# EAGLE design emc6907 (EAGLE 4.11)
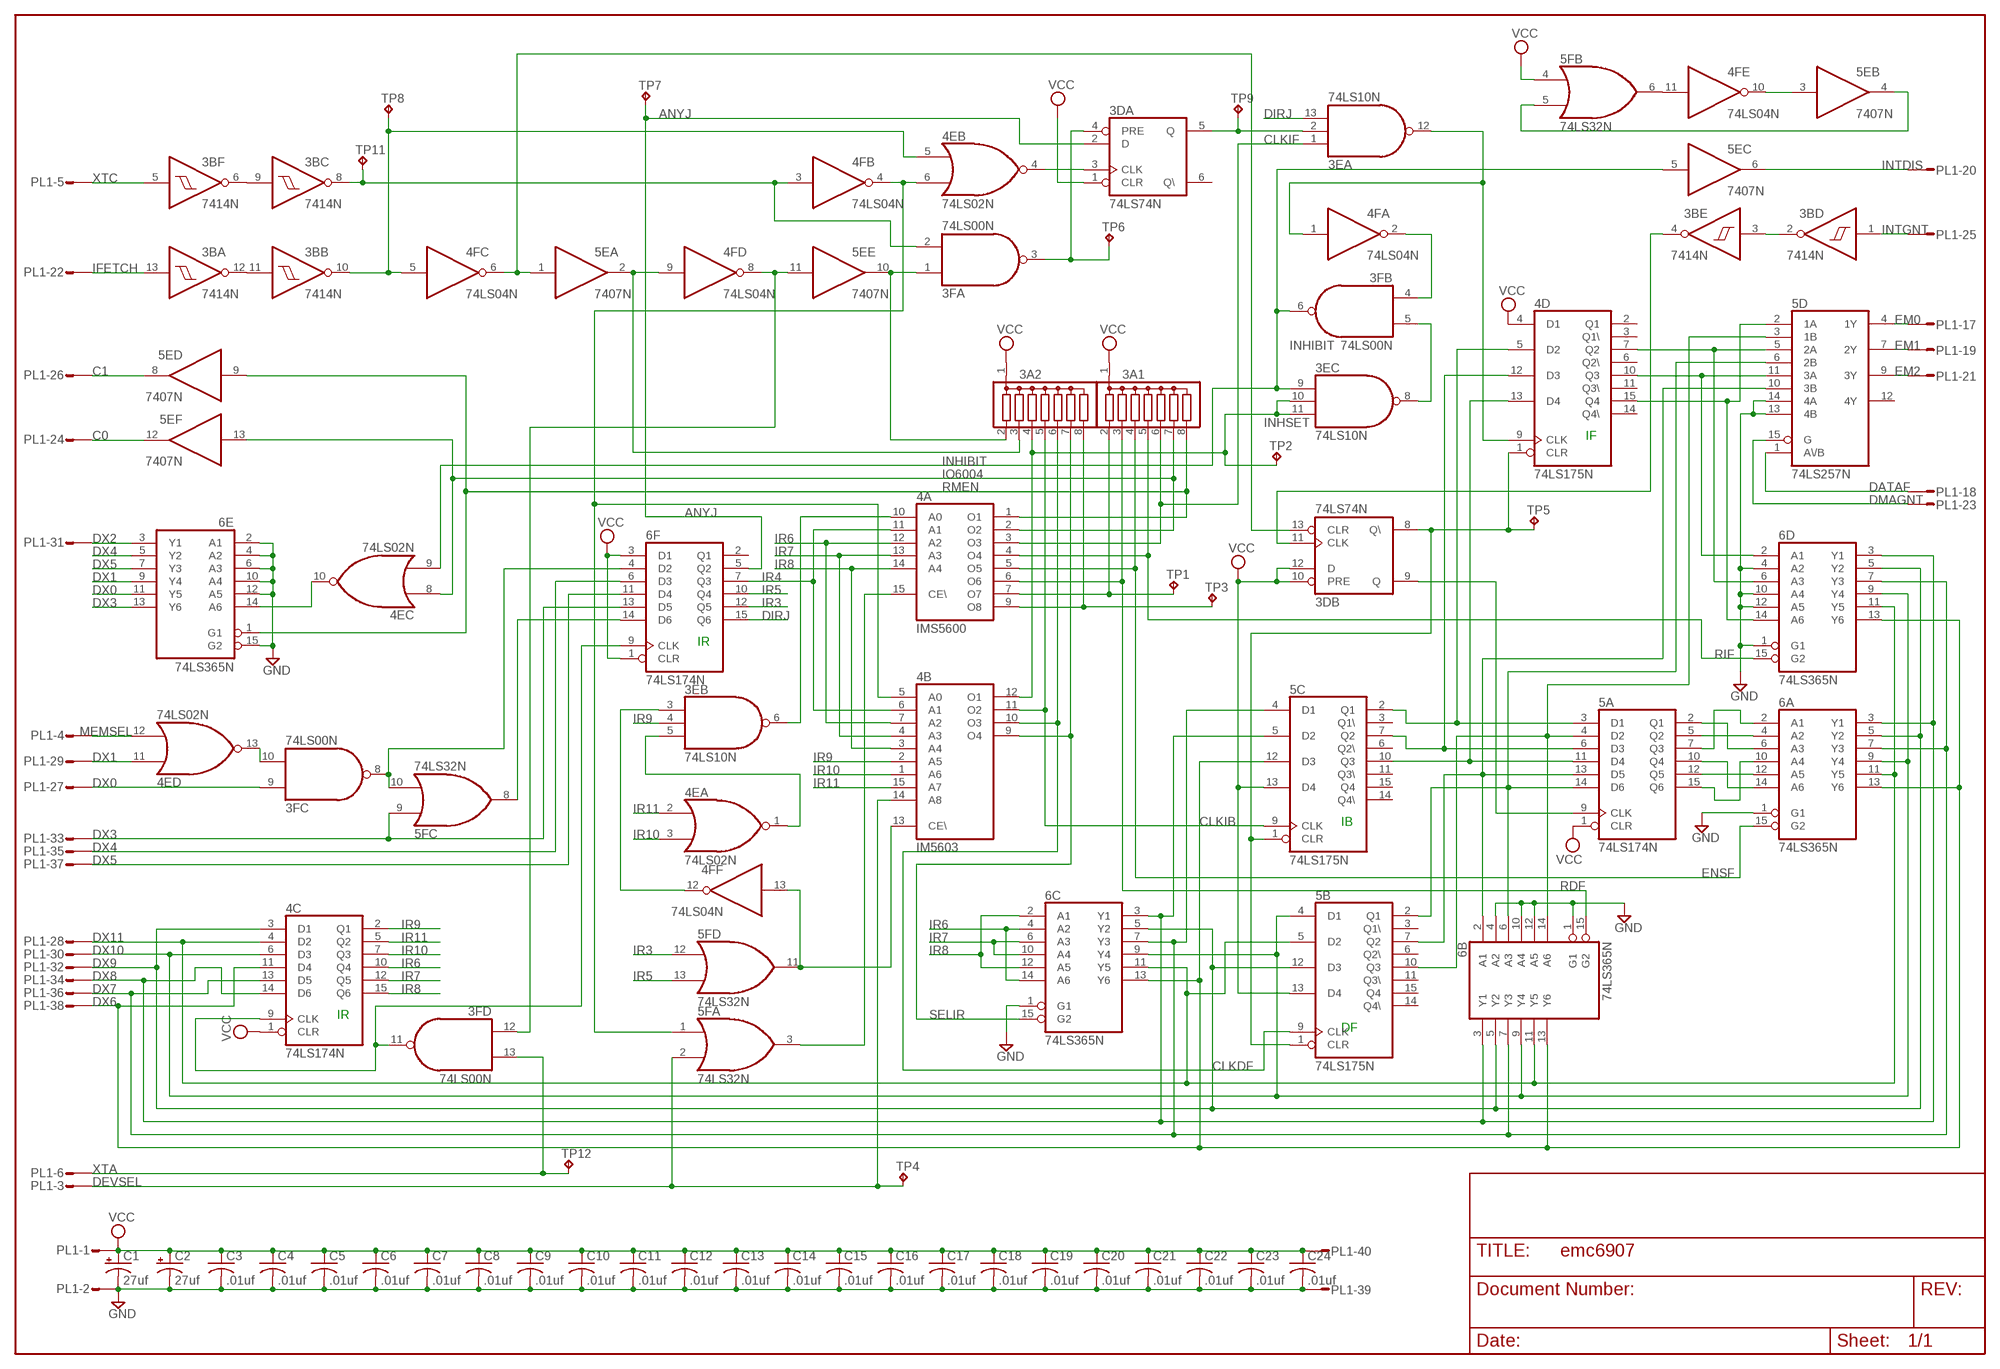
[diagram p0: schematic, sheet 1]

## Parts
3A1  G07R  [SIL8]
3A2  G07R  [SIL8]
3B  7414N  [DIL14]
3D  74LS74N  [DIL14]
3E  74LS10N  [DIL14]
3F  74LS00N  [DIL14]
4A  IMS5600  5600  [DIL16]
4B  IM5603  5306  [DIL16]
4C  74LS174N  [DIL16]
4D  74LS175N  [DIL16]
4E  74LS02N  [DIL14]
4F  74LS04N  [DIL14]
5A  74LS174N  [DIL16]
5B  74LS175N  [DIL16]
5C  74LS175N  [DIL16]
5D  74LS257N  [DIL16]
5E  7407N  [DIL14]
5F  74LS32N  [DIL14]
6A  74LS365N  [DIL16]
6B  74LS365N  [DIL16]
6C  74LS365N  [DIL16]
6D  74LS365N  [DIL16]
6E  74LS365N  [DIL16]
6F  74LS174N  [DIL16]
C1  27uf  CPOL-USE22-6AXIAL  [E22-6]
C2  27uf  CPOL-USE22-6AXIAL  [E22-6]
C3  .01uf  C-US050-025X075  [C050-025X075]
C4  .01uf  C-US050-025X075  [C050-025X075]
C5  .01uf  C-US050-025X075  [C050-025X075]
C6  .01uf  C-US050-025X075  [C050-025X075]
C7  .01uf  C-US050-025X075  [C050-025X075]
C8  .01uf  C-US050-025X075  [C050-025X075]
C9  .01uf  C-US050-025X075  [C050-025X075]
C10  .01uf  C-US050-025X075  [C050-025X075]
C11  .01uf  C-US050-025X075  [C050-025X075]
C12  .01uf  C-US050-025X075  [C050-025X075]
C13  .01uf  C-US050-025X075  [C050-025X075]
C14  .01uf  C-US050-025X075  [C050-025X075]
C15  .01uf  C-US050-025X075  [C050-025X075]
C16  .01uf  C-US050-025X075  [C050-025X075]
C17  .01uf  C-US050-025X075  [C050-025X075]
C18  .01uf  C-US050-025X075  [C050-025X075]
C19  .01uf  C-US050-025X075  [C050-025X075]
C20  .01uf  C-US050-025X075  [C050-025X075]
C21  .01uf  C-US050-025X075  [C050-025X075]
C22  .01uf  C-US050-025X075  [C050-025X075]
C23  .01uf  C-US050-025X075  [C050-025X075]
C24  .01uf  C-US050-025X075  [C050-025X075]
PL1  40VS  [40V]
TP1  TPPAD1-13  [P1-13]
TP2  TPPAD1-13  [P1-13]
TP3  TPPAD1-13  [P1-13]
TP4  TPPAD1-13  [P1-13]
TP5  TPPAD1-13  [P1-13]
TP6  TPPAD1-13  [P1-13]
TP7  TPPAD1-13  [P1-13]
TP8  TPPAD1-13  [P1-13]
TP9  TPPAD1-13  [P1-13]
TP11  TPPAD1-13  [P1-13]
TP12  TPPAD1-13  [P1-13]

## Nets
ANYJ: 3D.2(A:D) 6F.5(Q2) TP7.1(TP)
C0: 5E.12(F:O) PL1.24
C1: 5E.8(D:O) PL1.26
CLKDF: 3A2.6 4B.10(O3) 5B.9(CLK)
CLKIB: 3A2.5 4B.11(O2) 5C.9(CLK)
CLKIF: 3A1.6 3E.1(A:I0) 4A.3(O3)
DATAF: 5D.1(A\/B) PL1.18
DEVSEL: 4B.14(A8) 5F.2(A:I1) PL1.3 TP4.1(TP)
DIRJ: 3E.13(A:I2) 6F.15(Q6)
DMAGNT: 5D.15(G) PL1.23
DX0: 3F.9(C:I0) 6E.11(Y5) PL1.27
DX1: 4E.11(D:I0) 6E.9(Y4) PL1.29
DX2: 6E.3(Y1) PL1.31
DX3: 5F.9(C:I0) 6E.13(Y6) 6F.13(D5) PL1.33
DX4: 6E.5(Y2) 6F.6(D3) PL1.35
DX5: 6E.7(Y3) 6F.11(D4) PL1.37
DX6: 4C.11(D4) 5C.12(D3) 6A.13(Y6) 6B.13(Y6) 6C.13(Y6) 6D.13(Y6) PL1.38
DX7: 4C.13(D5) 5C.4(D1) 6A.7(Y3) 6B.7(Y3) 6C.7(Y3) 6D.7(Y3) PL1.36
DX8: 4C.14(D6) 5C.5(D2) 6A.3(Y1) 6B.3(Y1) 6C.3(Y1) 6D.3(Y1) PL1.34
DX9: 4C.3(D1) 5B.12(D3) 6A.5(Y2) 6B.5(Y2) 6C.5(Y2) 6D.5(Y2) PL1.32
DX10: 4C.6(D3) 5B.4(D1) 6A.9(Y4) 6B.9(Y4) 6C.9(Y4) 6D.9(Y4) PL1.30
DX11: 4C.4(D2) 5B.5(D2) 6A.11(Y5) 6B.11(Y5) 6C.11(Y5) 6D.11(Y5) PL1.28
EM0: 5D.4(1Y) PL1.17
EM1: 5D.7(2Y) PL1.19
EM2: 5D.9(3Y) PL1.21
ENSF: 3A1.4 4A.5(O5) 6A.15(G2)
GND: 5D.13(4B) 5D.14(4A) 6A.1(G1) 6B.1(G1) 6B.4(A2) 6B.10(A4) 6B.12(A5) 6C.1(G1) 6D.1(G1) 6D.4(A2) 6D.10(A4) 6D.12(A5) 6E.2(A1) 6E.4(A2) 6E.6(A3) 6E.10(A4) 6E.12(A5) 6E.15(G2) C1.- C2.- C3.2 C4.2 C5.2 C6.2 C7.2 C8.2 C9.2 C10.2 C11.2 C12.2 C13.2 C14.2 C15.2 C16.2 C17.2 C18.2 C19.2 C20.2 C21.2 C22.2 C23.2 C24.2 PL1.2 PL1.39
IFETCH: 3B.13(A:I) PL1.22
INHIBIT: 3E.9(C:I0) 3F.6(B:O) 4E.9(C:I1) 5E.5(C:I)
INHSET: 3A2.4 3E.10(C:I1) 3E.11(C:I2) 4B.12(O1) TP2.1(TP)
INTDIS: 5E.6(C:O) PL1.20
INTGNT: 3B.1(D:I) PL1.25
IO6004: 3A1.7 4A.2(O2) 4E.8(C:I0) 5E.13(F:I)
IR3: 5F.12(D:I0) 6F.12(Q5)
IR4: 4A.11(A1) 4B.6(A1) 6F.7(Q3)
IR5: 5F.13(D:I1) 6F.10(Q4)
IR6: 4A.12(A2) 4B.7(A2) 4C.10(Q4) 6C.4(A2) 6C.14(A6)
IR7: 4A.13(A3) 4B.4(A3) 4C.12(Q5) 6C.6(A3) 6C.10(A4)
IR8: 4A.14(A4) 4B.3(A4) 4C.15(Q6) 6C.2(A1) 6C.12(A5)
IR9: 3E.4(B:I1) 4B.2(A5) 4C.2(Q1)
IR10: 4B.1(A6) 4C.7(Q3) 4E.3(A:I1)
IR11: 4B.15(A7) 4C.5(Q2) 4E.2(A:I0)
LOADIR: 3F.11(D:O) 4C.9(CLK) 6F.9(CLK)
MEMSEL: 4E.12(D:I1) PL1.4
N$1: 3B.11(B:I) 3B.12(A:O)
N$2: 3B.6(F:O) 3B.9(C:I)
N$3: 3B.8(C:O) 3F.2(A:I1) 4F.3(B:I) TP11.1(TP)
N$4: 3B.10(B:O) 4E.5(B:I0) 4F.5(C:I) TP8.1(TP)
N$5: 3D.13(B:CLR) 4F.6(C:O) 5E.1(A:I)
N$6: 3D.5(A:Q) 3E.2(A:I1) TP9.1(TP)
N$7: 3A2.2 3F.1(A:I0) 5E.10(E:O)
N$8: 3F.12(D:I0) 4F.8(D:O) 5E.11(E:I)
N$9: 3A2.3 4F.9(D:I) 5E.2(A:O)
N$10: 4B.5(A0) 4E.6(B:I1) 4F.4(B:O) 5F.1(A:I0)
N$11: 3D.3(A:CLK) 4E.4(B:O)
N$12: 3D.4(A:PRE) 3F.3(A:O) TP6.1(TP)
N$13: 4F.11(E:I) 5F.6(B:O)
N$14: 3F.10(C:I1) 4E.13(D:O)
N$15: 4E.10(C:O) 6E.14(A6)
N$16: 5E.4(B:O) 5F.5(B:I1)
N$17: 4F.10(E:O) 5E.3(B:I)
N$18: 3F.8(C:O) 5F.10(C:I1) 6F.4(D2)
N$19: 5F.8(C:O) 6F.14(D6)
N$20: 4B.13(CE\) 4F.13(F:I) 5F.11(D:O)
N$28: 3A1.2 4A.7(O7) TP1.1(TP)
N$29: 3A2.8 4A.9(O8) TP3.1(TP)
N$35: 3E.3(B:I0) 4F.12(F:O)
N$36: 3E.6(B:O) 4A.10(A0)
N$37: 4A.15(CE\) 5F.3(A:O)
N$38: 5A.2(Q1) 6A.6(A3)
N$39: 3E.5(B:I2) 4E.1(A:O)
N$40: 5A.10(Q4) 6A.14(A6)
N$41: 5A.7(Q3) 6A.2(A1)
N$42: 5A.5(Q2) 6A.4(A2)
N$43: 5A.15(Q6) 6A.10(A4)
N$44: 5A.12(Q5) 6A.12(A5)
N$45: 4D.15(Q4) 5D.2(1A) 6D.14(A6)
N$46: 4D.10(Q3) 5D.11(3A) 6D.2(A1)
N$47: 4D.7(Q2) 5D.5(2A) 6D.6(A3)
N$48: 3D.8(B:Q\) 4D.1(CLR) 5B.1(CLR) 5C.1(CLR) TP5.1(TP)
N$50: 4D.13(D4) 5A.11(D4) 5C.10(Q3)
N$51: 4D.5(D2) 5A.3(D1) 5C.2(Q1)
N$52: 4D.12(D3) 5A.6(D3) 5C.7(Q2)
N$53: 5A.4(D2) 5B.10(Q3) 5D.3(1B) 6B.14(A6)
N$54: 5A.14(D6) 5B.2(Q1) 5D.6(2B) 6B.6(A3)
N$55: 5A.13(D5) 5B.7(Q2) 5D.10(3B) 6B.2(A1)
N$59: 3D.9(B:Q) 5A.9(CLK)
N$61: 3E.12(A:O) 4D.9(CLK) 4F.1(A:I)
N$70: 3E.8(C:O) 3F.5(B:I1)
N$71: 3F.4(B:I0) 4F.2(A:O)
N$72: 3B.2(D:O) 3B.3(E:I)
N$74: 3B.4(E:O) 3D.11(B:CLK)
RDF: 3A1.3 4A.6(O6) 6B.15(G2)
RIF: 3A1.5 4A.4(O4) 6D.15(G2)
RMEN: 3A1.8 4A.1(O1) 5E.9(D:I) 6E.1(G1)
SELIR: 3A2.7 4B.9(O4) 6C.15(G2)
VCC: 3A1.1 3A2.1 3D.1(A:CLR) 3D.10(B:PRE) 3D.12(B:D) 4C.1(CLR) 4D.4(D1) 5A.1(CLR) 5B.13(D4) 5C.13(D4) 5F.4(B:I0) 6F.1(CLR) 6F.3(D1) C1.+ C2.+ C3.1 C4.1 C5.1 C6.1 C7.1 C8.1 C9.1 C10.1 C11.1 C12.1 C13.1 C14.1 C15.1 C16.1 C17.1 C18.1 C19.1 C20.1 C21.1 C22.1 C23.1 C24.1 PL1.1 PL1.40
XTA: 3F.13(D:I1) PL1.6 TP12.1(TP)
XTC: 3B.5(F:I) PL1.5
Unconnected: 3D.6(A:Q\) 4D.2(Q1) 4D.3(Q1\) 4D.6(Q2\) 4D.11(Q3\) 4D.14(Q4\) 5B.3(Q1\) 5B.6(Q2\) 5B.11(Q3\) 5B.14(Q4\) 5B.15(Q4) 5C.3(Q1\) 5C.6(Q2\) 5C.11(Q3\) 5C.14(Q4\) 5C.15(Q4) 5D.12(4Y) 6F.2(Q1) PL1.7 PL1.8 PL1.9 PL1.10 PL1.11 PL1.12 PL1.13 PL1.14 PL1.15 PL1.16

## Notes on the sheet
- IF
- IR
- IB
- IR
- DF

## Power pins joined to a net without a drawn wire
GND: 3B.7(P:GND) 3D.7(P:GND) 3E.7(P:GND) 3F.7(P:GND) 4A.8(GND) 4B.8(GND) 4C.8(GND) 4D.8(GND) 4E.7(P:GND) 4F.7(P:GND) 5A.8(GND) 5B.8(GND) 5C.8(GND) 5D.8(GND) 5E.7(P:GND) 5F.7(P:GND) 6A.8(GND) 6B.8(GND) 6C.8(GND) 6D.8(GND) 6E.8(GND) 6F.8(GND)
VCC: 3B.14(P:VCC) 3D.14(P:VCC) 3E.14(P:VCC) 3F.14(P:VCC) 4A.16(VCC) 4B.16(VCC) 4C.16(VCC) 4D.16(VCC) 4E.14(P:VCC) 4F.14(P:VCC) 5A.16(VCC) 5B.16(VCC) 5C.16(VCC) 5D.16(VCC) 5E.14(P:VCC) 5F.14(P:VCC) 6A.16(VCC) 6B.16(VCC) 6C.16(VCC) 6D.16(VCC) 6E.16(VCC) 6F.16(VCC)

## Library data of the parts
3A1 3A2 = resistor-sil:G07R: SIL RESISTOR
3B = 74xx-jameco:74*14: Hex schmitt trigger INVERTER
3D = 74xx-jameco:74*74: Dual D type positive edge triggered FLIP FLOP, preset and clear
3E = 74xx-jameco:74*10: Triple 3-input NAND gate
3F = 74xx-jameco:74*00: Quad 2-input NAND gate
4A = memory:5600: MEMORY
4B = memory:5306: MEMORY
4C 5A 6F = 74xx-jameco:74*174: Hex D type FLIP FLOP, clear
4D 5B 5C = 74xx-jameco:74*175: Qadruple D type FLIP FLOP, clear
4E = 74xx-jameco:74*02: Quad 2-input NOR gate
4F = 74xx-jameco:74*04: Hex INVERTER
5D = 74xx-jameco:74*257: Quadruple 2-to 1 line data SELECTOR/MULTIPLEXER
5E = 74xx-jameco:74*07: Hex BUFFER, open collector high-voltage output
5F = 74xx-jameco:74*32: Quad 2-input OR gate
6A 6B 6C 6D 6E = 74xx-jameco:74*365: Hex BUS DRIVER, 3-state
C1 C2 = rcl:CPOL-US: POLARIZED CAPACITOR, American symbol
C3-C24 = rcl:C-US: CAPACITOR, American symbol
PL1 = con-harting-v:40VS: CONNECTOR
TP1-TP9 TP11 TP12 = testpad:TP

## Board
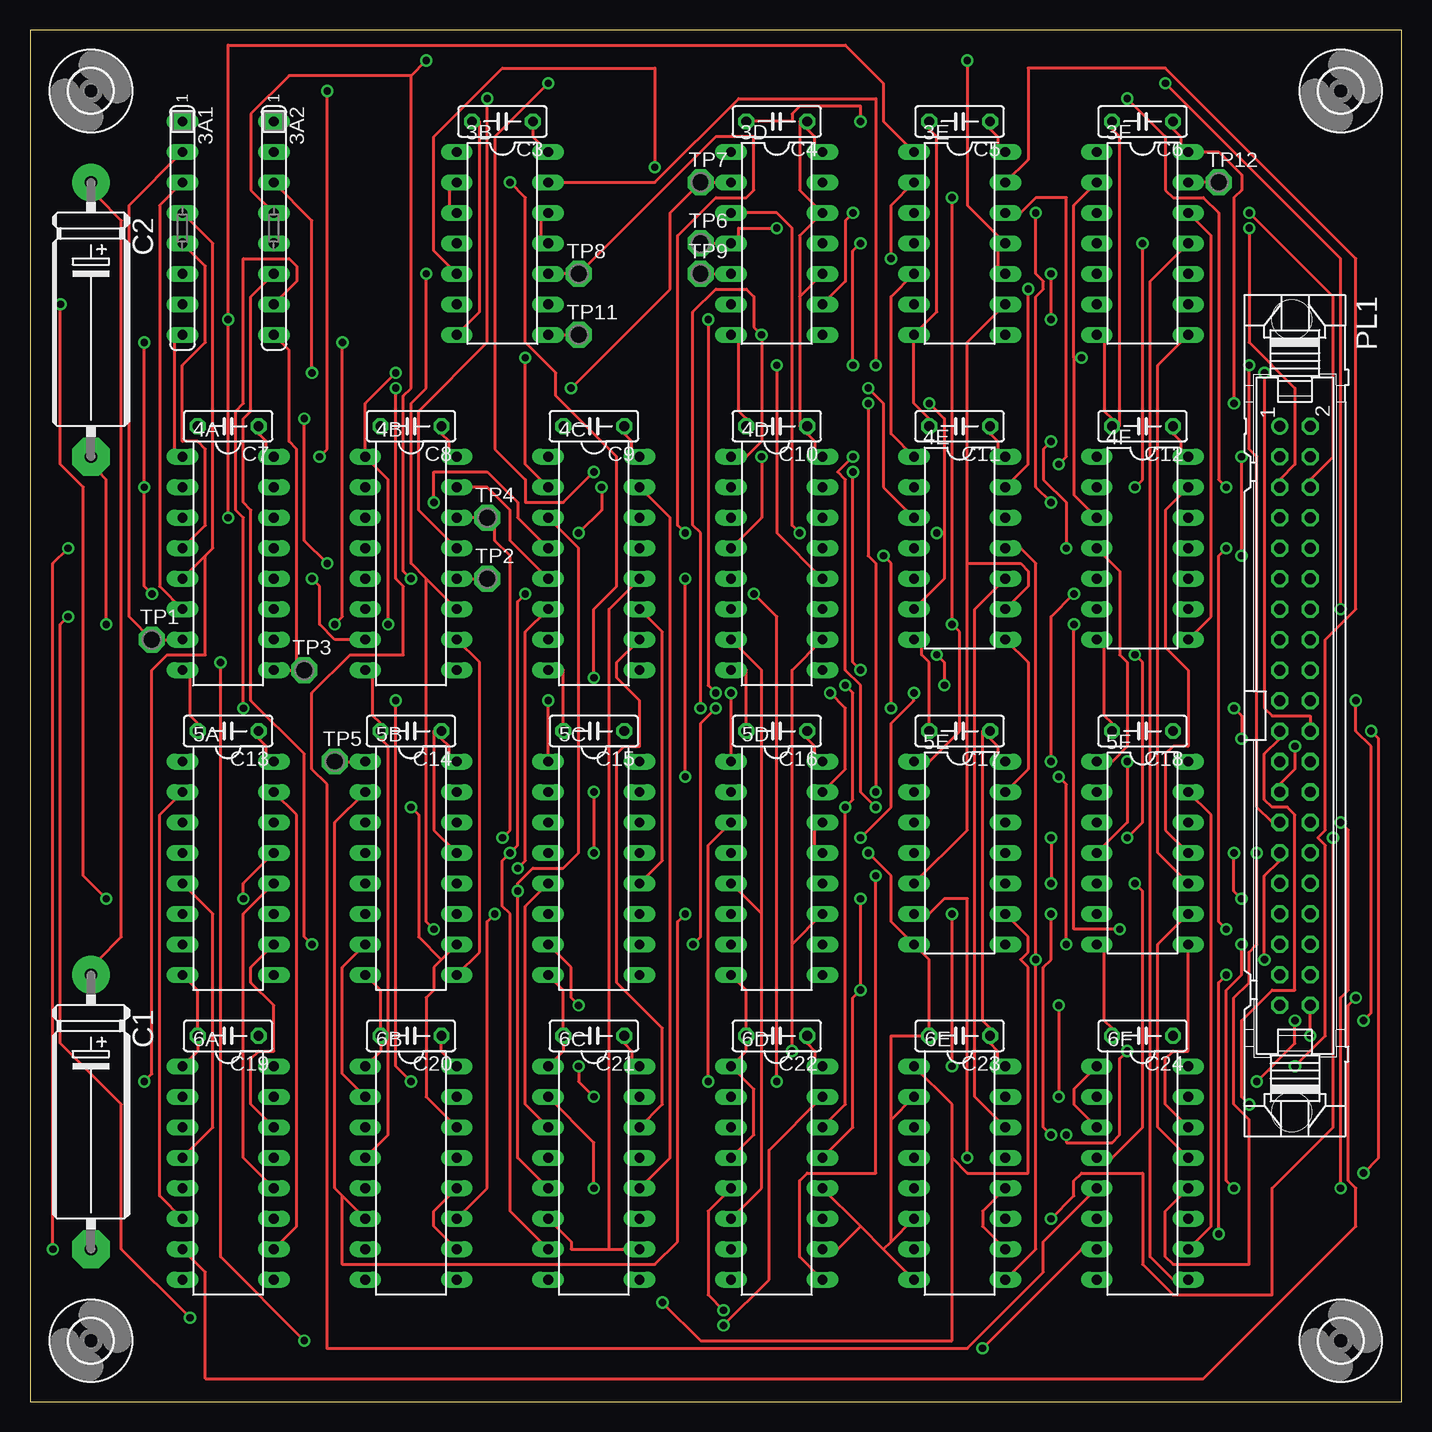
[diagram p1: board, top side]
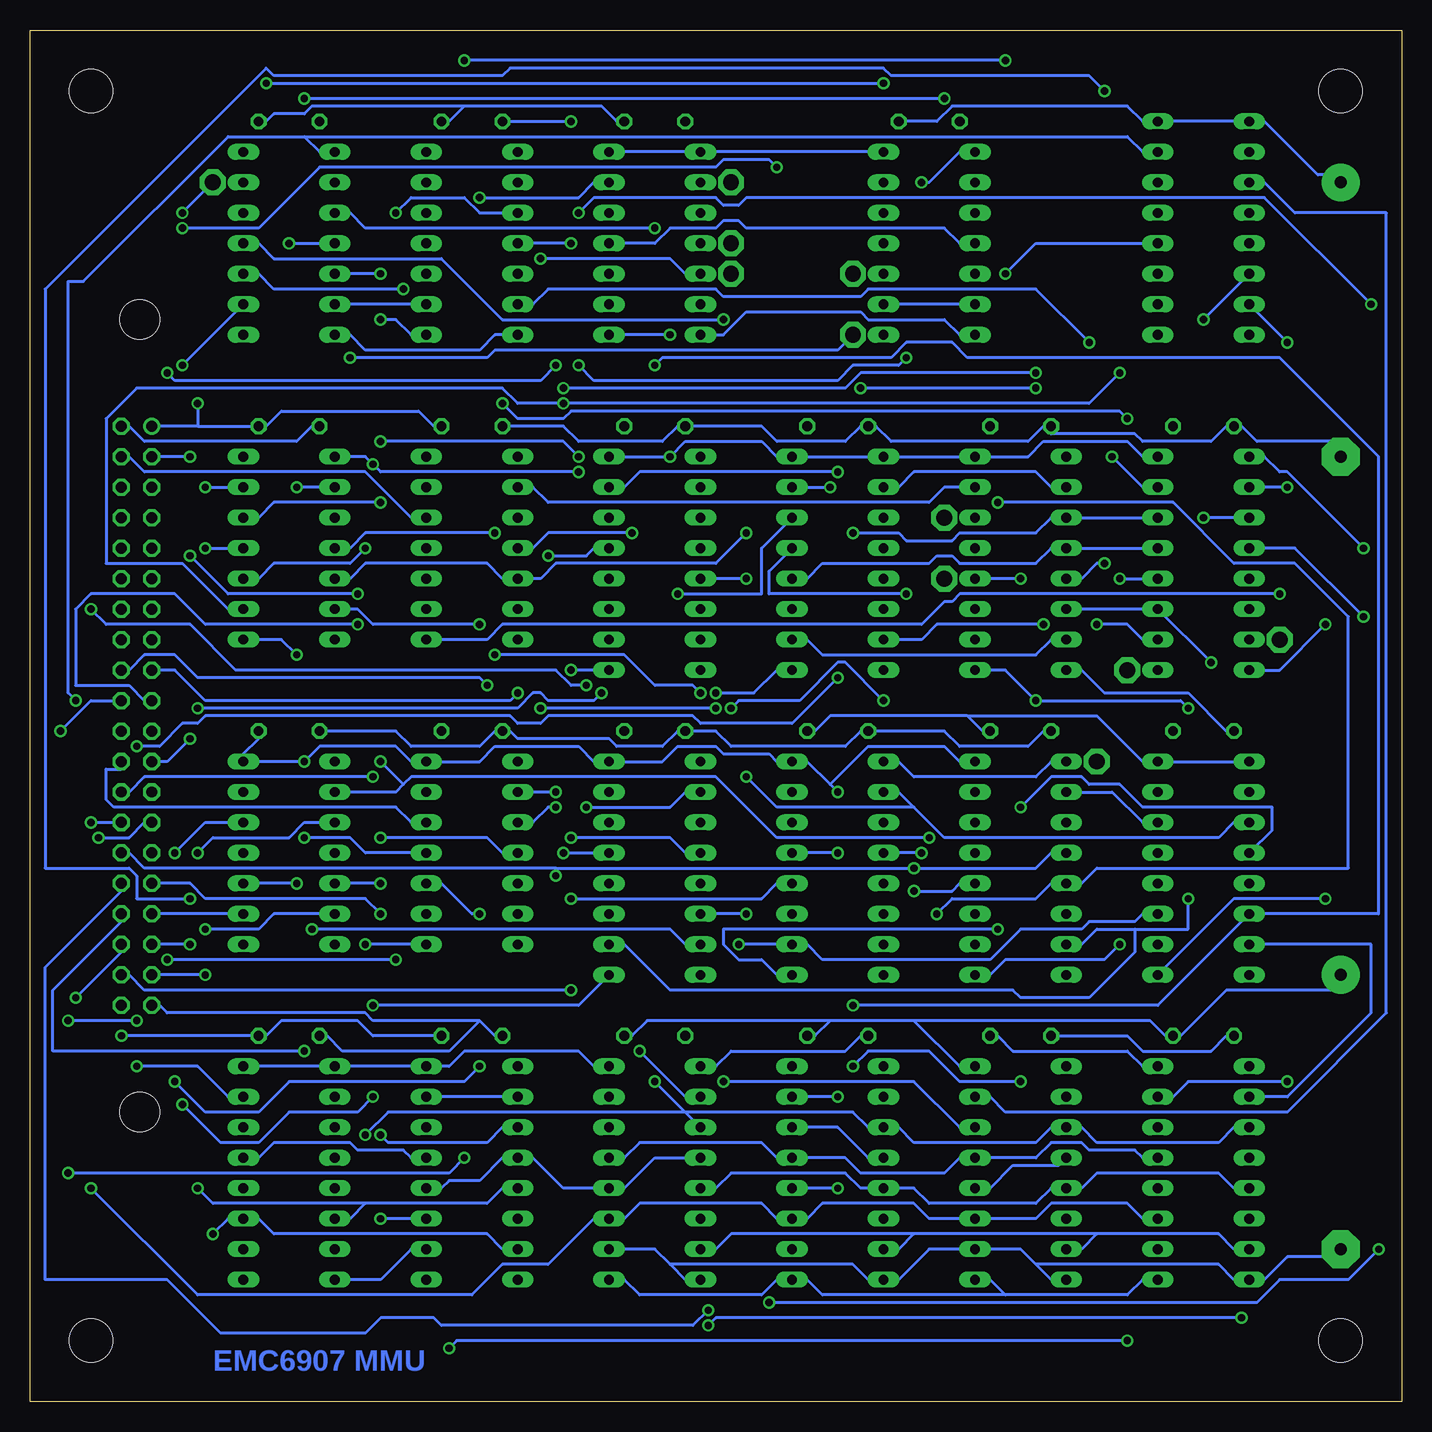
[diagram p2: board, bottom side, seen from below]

Size 114.3 x 114.3 mm. Coordinates in mm from the lower left corner, seen from the top.
Outline: 0,0 114.3,0 114.3,114.3 0,114.3 0,0
Copper layers (1*16): Top 0.035mm / dielectric 1.5mm / Bottom 0.035mm
Design rules "10mils": minimum track width 10mil, minimum drill 24mil, track to track 10mil, track to pad 10mil, pad to pad 10mil, via to via 10mil, smd to smd 10mil, copper to edge 40mil, drill to drill 10mil, minimum pad ring 10mil, minimum via ring 8mil, stop-mask expansion 0mil, vias tented up to drill 0mil, thermal gap 10mil

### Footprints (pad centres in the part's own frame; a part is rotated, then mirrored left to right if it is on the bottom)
SIL8 = drill 0.813 long: 1 -8.89,0; 2 -6.35,0; 3 -3.81,0; 4 -1.27,0; 5 1.27,0; 6 3.81,0; 7 6.35,0; 8 8.89,0
DIL14 = drill 0.813 long: 1 -7.62,-3.81; 2 -5.08,-3.81; 3 -2.54,-3.81; 4 0,-3.81; 5 2.54,-3.81; 6 5.08,-3.81; 7 7.62,-3.81; 8 7.62,3.81; 9 5.08,3.81; 10 2.54,3.81; 11 0,3.81; 12 -2.54,3.81; 13 -5.08,3.81; 14 -7.62,3.81
DIL16 = drill 0.813 long: 1 -8.89,-3.81; 2 -6.35,-3.81; 3 -3.81,-3.81; 4 -1.27,-3.81; 5 1.27,-3.81; 6 3.81,-3.81; 7 6.35,-3.81; 8 8.89,-3.81; 9 8.89,3.81; 10 6.35,3.81; 11 3.81,3.81; 12 1.27,3.81; 13 -1.27,3.81; 14 -3.81,3.81; 15 -6.35,3.81; 16 -8.89,3.81
E22-6 = drill 1.016 pad 3.15 round: + -11.43,0 | drill 1.016 pad 3.15 octagon: - 11.43,0
C050-025X075 = drill 0.813 octagon: 1 -2.54,0; 2 2.54,0
40V = drill 0.914 round: 1 -24.13,-1.27 | drill 0.914 octagon: 2 -24.13,1.27; 3 -21.59,-1.27; 4 -21.59,1.27; 5 -19.05,-1.27; 6 -19.05,1.27; 7 -16.51,-1.27; 8 -16.51,1.27; 9 -13.97,-1.27; 10 -13.97,1.27; 11 -11.43,-1.27; 12 -11.43,1.27; 13 -8.89,-1.27; 14 -8.89,1.27; 15 -6.35,-1.27; 16 -6.35,1.27; 17 -3.81,-1.27; 18 -3.81,1.27; 19 -1.27,-1.27; 20 -1.27,1.27; 21 1.27,-1.27; 22 1.27,1.27; 23 3.81,-1.27; 24 3.81,1.27; 25 6.35,-1.27; 26 6.35,1.27; 27 8.89,-1.27; 28 8.89,1.27; 29 11.43,-1.27; 30 11.43,1.27; 31 13.97,-1.27; 32 13.97,1.27; 33 16.51,-1.27; 34 16.51,1.27; 35 19.05,-1.27; 36 19.05,1.27; 37 21.59,-1.27; 38 21.59,1.27; 39 24.13,-1.27; 40 24.13,1.27 | hole 3.302: 33.02,-0.254; -33.02,-0.254
P1-13 = drill 1.321 pad 2.159 octagon: 1 0,0
3,6 = hole 3.6: 0,0

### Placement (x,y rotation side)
3A1  12.7,97.79 270 top
3A2  20.32,97.79 270 top
3B  39.37,96.52 270 top
3D  62.23,96.52 270 top
3E  77.47,96.52 270 top
3F  92.71,96.52 270 top
4A  16.51,69.85 270 top
4B  31.75,69.85 270 top
4C  46.99,69.85 270 top
4D  62.23,69.85 270 top
4E  77.47,71.12 270 top
4F  92.71,71.12 270 top
5A  16.51,44.45 270 top
5B  31.75,44.45 270 top
5C  46.99,44.45 270 top
5D  62.23,44.45 270 top
5E  77.47,45.72 270 top
5F  92.71,45.72 270 top
6A  16.51,19.05 270 top
6B  31.75,19.05 270 top
6C  46.99,19.05 270 top
6D  62.23,19.05 270 top
6E  77.47,19.05 270 top
6F  92.71,19.05 270 top
C1  5.08,24.13 270 top
C2  5.08,90.17 270 top
C3  39.37,106.68 180 top
C4  62.23,106.68 180 top
C5  77.47,106.68 180 top
C6  92.71,106.68 180 top
C7  16.51,81.28 180 top
C8  31.75,81.28 180 top
C9  46.99,81.28 180 top
C10  62.23,81.28 180 top
C11  77.47,81.28 180 top
C12  92.71,81.28 180 top
C13  16.51,55.88 180 top
C14  31.75,55.88 180 top
C15  46.99,55.88 180 top
C16  62.23,55.88 180 top
C17  77.47,55.88 180 top
C18  92.71,55.88 180 top
C19  16.51,30.48 180 top
C20  31.75,30.48 180 top
C21  46.99,30.48 180 top
C22  62.23,30.48 180 top
C23  77.47,30.48 180 top
C24  92.71,30.48 180 top
PL1  105.41,57.15 270 top
TP1  10.16,63.5 0 top
TP2  38.1,68.58 0 top
TP3  22.86,60.96 0 top
TP4  38.1,73.66 0 top
TP5  25.4,53.34 0 top
TP6  55.88,96.52 0 top
TP7  55.88,101.6 0 top
TP8  45.72,93.98 0 top
TP9  55.88,93.98 0 top
TP11  45.72,88.9 0 top
TP12  99.06,101.6 0 top
U$1  [3,6]  5.08,109.22 0 top
U$2  [3,6]  109.22,109.22 0 top
U$3  [3,6]  5.08,5.08 0 top
U$4  [3,6]  109.22,5.08 0 top

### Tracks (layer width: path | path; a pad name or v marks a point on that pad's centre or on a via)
ANYJ  (via drill 0.61)
  Top 0.254: 3D.2 TP7.1 53.34,99.06 53.34,92.71 v45.09,84.45 | v30.48,84.45 30.48,68.58 31.11,67.94 31.11,62.23 26.67,62.23 23.5,59.05 23.5,52.7 24.77,51.44 24.77,4.45 78.11,4.45 84.45,10.79 84.45,13.34 6F.5
  Bottom 0.254: v30.48,84.45 v45.09,84.45
C0
  Bottom 0.254: 5E.12 82.55,48.26 83.82,49.53 107.31,49.53 107.95,50.16 107.95,52.7 106.68,52.7 PL1.24
C1  (via drill 0.61)
  Top 0.254: v86.36,38.1 86.36,51.44 v85.72,52.07
  Bottom 0.254: v85.72,52.07 104.78,52.07 106.05,50.8 PL1.26 | 5E.8 v86.36,38.1
CLKDF  (via drill 0.61)
  Top 0.254: 5B.9 37.47,37.47 37.47,61.59 4B.10 | v23.5,38.1 22.86,38.73 22.86,53.98 18.41,58.42 18.41,74.3 17.78,74.93 17.78,81.92 18.41,82.55 18.41,92.08 3A2.6
  Bottom 0.254: v23.5,38.1 24.77,36.83 33.02,36.83 34.29,35.56 5B.9
CLKIB  (via drill 0.61)
  Top 0.254: 33.02,68.58 31.75,69.85 31.75,83.19 33.02,84.45 v33.02,93.98 | 33.02,68.58 4B.11 | v33.66,39.37 33.02,40.01 33.02,68.58
  Bottom 0.254: v33.02,93.98 30.48,96.52 3A2.5 | v33.66,39.37 56.52,39.37 56.52,38.1 55.24,36.83 53.34,36.83 52.07,35.56 5C.9
CLKIF  (via drill 0.61)
  Top 0.254: v16.51,73.66 v16.51,90.17 16.51,113.03 67.94,113.03 71.12,109.86 71.12,106.68 3E.1
  Bottom 0.254: 4A.3 v16.51,73.66 | v16.51,90.17 3A1.6
DATAF  (via drill 0.61)
  Top 0.254: v75.56,62.23 76.2,61.59 v76.2,59.69 | 5D.1 v58.42,59.05
  Bottom 0.254: v58.42,59.05 59.05,59.69 62.23,59.69 64.77,62.23 v75.56,62.23 | v76.2,59.69 76.83,60.33 100.33,60.33 102.23,62.23 104.78,62.23 106.05,60.96 PL1.18
DEVSEL  (via drill 0.61)
  Top 0.254: v39.37,46.99 40.01,47.62 40.01,70.48 38.73,71.75 38.73,73.03 TP4.1 4B.14 | v100.97,70.48 v100.97,78.74 | v87,67.31 85.09,65.41 v85.09,53.34
  Bottom 0.254: 83.19,51.44 82.55,52.07 57.15,52.07 52.07,46.99 v39.37,46.99 | 83.19,51.44 83.82,50.8 5F.2 | v100.97,70.48 97.79,67.31 v87,67.31 | 83.19,51.44 v85.09,53.34 | v100.97,78.74 PL1.3
DIRJ  (via drill 0.61)
  Top 0.254: v105.41,27.94 107.95,30.48 107.95,46.35 107.31,46.99 107.95,47.62 107.95,63.5 110.49,66.04 110.49,95.25 94.61,111.12 83.19,111.12 83.19,103.5 3E.13
  Bottom 0.254: v105.41,27.94 100.33,27.94 97.79,25.4 6F.15
DMAGNT  (via drill 0.61)
  Top 0.254: v66.67,59.05 67.94,57.78 67.94,52.7 5D.15 | v100.33,57.78 100.97,57.15 v100.97,55.24
  Bottom 0.254: v66.67,59.05 67.31,58.42 71.12,58.42 71.75,59.05 72.39,59.05 73.66,57.78 v100.33,57.78 | v100.97,55.24 102.87,53.34 PL1.23
DX0  (via drill 0.61)
  Top 0.254: v85.09,15.24 87,17.14 87,18.41 87.63,19.05 92.71,19.05 92.71,11.43 95.25,8.89 103.5,8.89 103.5,17.78 108.58,22.86 v108.58,46.99 | v101.6,86.36 101.6,79.38 102.23,78.74 102.23,49.53 103.5,48.26 PL1.27
  Bottom 0.254: v108.58,46.99 106.05,46.99 104.78,48.26 PL1.27 | 6E.11 v85.09,15.24 | v101.6,86.36 3F.9
DX1  (via drill 0.61)
  Top 0.254: 6E.9 83.82,12.7 v83.82,36.83 83.82,69.85 82.55,71.12 4E.11 | v102.87,36.83 102.87,43.81 104.14,45.09 PL1.29
  Bottom 0.254: v83.82,36.83 v102.87,36.83
DX2  (via drill 0.61)
  Top 0.254: v85.09,22.23 84.45,22.86 84.45,36.2 85.09,36.83 v85.09,40.64
  Bottom 0.254: v85.09,22.23 84.45,21.59 76.2,21.59 74.93,22.86 6E.3 | v85.09,40.64 86.36,41.91 99.69,41.91 100.97,43.18 PL1.31
DX3
  Top 0.254: 5F.9 93.98,38.1 93.98,22.86 6F.13
  Bottom 0.254: 5F.9 PL1.33 | 6E.13 82.55,20.32 83.19,20.95 87,20.95 87.63,21.59 93.98,21.59 95.25,20.32 6F.13
DX4  (via drill 0.61)
  Top 0.254: v100.97,38.1 100.97,35.56 99.69,34.29 99.69,18.41 v100.33,17.78
  Bottom 0.254: 86.36,16.51 76.2,16.51 74.93,17.78 6E.5 | 86.36,16.51 87.63,15.24 6F.6 | v100.33,17.78 99.06,16.51 86.36,16.51 | v100.97,38.1 PL1.35
DX5  (via drill 0.61)
  Top 0.254: v99.69,35.56 99.06,34.92 v99.06,13.97
  Bottom 0.254: 6E.7 74.93,12.7 76.2,13.97 93.98,13.97 95.25,15.24 6F.11 97.79,15.24 v99.06,13.97 | v99.69,35.56 PL1.37
DX6  (via drill 0.61)
  Top 0.254: 5C.12 52.7,45.09 52.7,64.14 4C.11 | 6D.13 68.58,22.86 68.58,33.66 v69.22,34.29 v69.22,41.91
  Bottom 0.254: 6A.13 21.59,20.32 22.23,20.95 26.04,20.95 26.67,21.59 29.21,21.59 30.48,20.32 6B.13 36.83,20.32 38.1,19.05 45.09,19.05 46.35,20.32 6C.13 52.07,20.32 53.34,21.59 63.5,21.59 64.77,20.32 6D.13 | v69.22,34.29 104.78,34.29 106.05,35.56 PL1.38 | v69.22,41.91 53.34,41.91 52.07,43.18 5C.12
DX7  (via drill 0.61)
  Top 0.254: 6C.7 40.01,15.88 40.01,40.64 39.37,41.27 39.37,45.09 v40.01,45.72 40.64,46.35 40.64,66.67 v41.27,67.31 | v110.49,33.66 109.86,33.02 109.86,18.41 110.49,17.78 110.49,14.61 97.79,1.91 14.61,1.91 14.61,10.79 6A.7
  Bottom 0.254: 25.4,13.97 15.24,13.97 13.97,12.7 6A.7 | 25.4,13.97 26.67,12.7 6B.7 | 40.64,13.97 41.91,12.7 6C.7 | 25.4,13.97 40.64,13.97 | v40.01,45.72 5C.4 | v41.27,67.31 52.7,67.31 52.7,69.22 4C.13 | 40.64,13.97 55.88,13.97 57.15,12.7 6D.7 | v110.49,33.66 106.68,37.47 PL1.36
DX8  (via drill 0.61)
  Top 0.254: 5C.5 41.27,41.27 41.27,24.77 6C.3 | v60.33,67.31 62.23,65.41 v62.23,26.67 | v91.44,29.21 90.81,28.57 90.81,22.23 90.17,21.59 86.36,21.59 v86.36,22.23
  Bottom 0.254: 6A.3 13.97,22.86 15.24,21.59 25.4,21.59 26.67,22.86 6B.3 29.21,22.86 30.48,21.59 40.64,21.59 41.91,22.86 6C.3 44.45,22.86 45.72,24.13 59.69,24.13 | v60.33,67.31 53.34,67.31 53.34,71.12 4C.14 | 59.69,24.13 v62.23,26.67 | 59.69,24.13 6D.3 | v91.44,29.21 112.39,29.21 112.39,34.29 106.68,40.01 PL1.34 | v86.36,22.23 84.45,24.13 59.69,24.13
DX9  (via drill 0.61)
  Top 0.254: 6C.5 40.64,20.32 v40.64,42.55 40.64,43.18 41.91,44.45 44.45,44.45 45.72,45.72 45.72,71.12 4C.3 | v57.78,7.62 56.52,8.89 56.52,15.88 6D.5
  Bottom 0.254: 6A.5 13.97,17.78 15.24,19.05 25.4,19.05 26.67,17.78 6B.5 29.21,17.78 30.48,16.51 39.37,16.51 40.64,17.78 6C.5 45.09,17.78 46.35,19.05 55.88,19.05 57.15,17.78 6D.5 | v40.64,42.55 37.47,42.55 36.83,43.18 5B.12 | v57.78,7.62 59.05,6.35 80.01,6.35 80.64,6.99 85.09,6.99 86.36,5.71 98.42,5.71 102.87,10.16 113.03,10.16 113.03,36.2 106.68,42.55 PL1.32
DX10  (via drill 0.61)
  Top 0.254: v40.64,44.45 41.27,45.09 41.27,64.14 4C.6 | v70.48,43.81 70.48,19.05 64.77,19.05 64.14,18.41 64.14,12.06 6D.9
  Bottom 0.254: 33.02,8.89 22.86,8.89 21.59,10.16 6A.9 | 33.02,8.89 34.29,10.16 6B.9 | 33.02,8.89 48.26,8.89 49.53,10.16 6C.9 52.07,10.16 53.34,8.89 63.5,8.89 64.77,10.16 6D.9 | 70.48,44.45 104.78,44.45 106.05,45.72 PL1.30 | 70.48,44.45 v40.64,44.45 30.48,44.45 29.21,45.72 5B.4 | v70.48,43.81 70.48,44.45
DX11  (via drill 0.61)
  Top 0.254: v109.22,48.26 109.86,47.62 109.86,34.29 109.22,33.66 v109.22,17.78 | v38.73,40.64 38.1,40.01 38.1,17.78 6B.11 | v33.66,74.93 33.66,77.47 38.1,77.47 40.64,74.93 40.64,73.66 4C.4
  Bottom 0.254: v109.22,17.78 100.33,8.89 77.47,8.89 74.93,11.43 71.12,11.43 67.31,15.24 6D.11 64.77,15.24 63.5,16.51 53.34,16.51 52.07,15.24 6C.11 49.53,15.24 48.26,16.51 40.64,16.51 39.37,15.24 6B.11 30.48,15.24 29.21,16.51 22.86,16.51 21.59,15.24 6A.11 | v109.22,48.26 PL1.28 | v38.73,40.64 37.47,41.91 30.48,41.91 29.21,43.18 5B.5 26.67,43.18 25.4,44.45 4.45,44.45 4.45,65.41 8.89,69.85 13.97,69.85 19.05,74.93 v33.66,74.93
EM0  (via drill 0.61)
  Top 0.254: v69.22,46.99 71.75,49.53 71.75,56.52 73.66,58.42 v73.66,59.05
  Bottom 0.254: v69.22,46.99 60.96,46.99 59.69,45.72 5D.4 | v73.66,59.05 74.3,58.42 99.69,58.42 102.23,60.96 PL1.17
EM1  (via drill 0.61)
  Top 0.254: v90.81,39.37 87,39.37 v87,64.77
  Bottom 0.254: v90.81,39.37 60.96,39.37 59.69,38.1 5D.7 | v87,64.77 99.69,64.77 102.23,67.31 109.22,67.31 110.49,66.04 110.49,59.69 106.05,59.69 104.78,58.42 PL1.19
EM2  (via drill 0.61)
  Top 0.254: v85.72,33.02 v85.72,25.4 | v101.6,24.77 100.97,25.4 100.97,31.75 103.5,34.29 105.41,34.29 105.41,48.9 104.78,49.53 103.5,49.53 102.87,50.16 102.87,53.98 104.14,55.24 PL1.21
  Bottom 0.254: v85.72,33.02 68.58,33.02 5D.9 | v85.72,25.4 87,24.13 92.71,24.13 95.25,21.59 98.42,21.59 v101.6,24.77
ENSF  (via drill 0.61)
  Top 0.254: 14.61,70.48 15.24,71.12 15.24,96.52 3A1.4 | 14.61,70.48 4A.5 | v9.53,26.67 10.16,27.3 10.16,60.96 11.43,62.23 14.61,62.23 14.61,70.48
  Bottom 0.254: v9.53,26.67 17.78,26.67 19.05,25.4 6A.15
GND  (via drill 0.61)
  Top 0.254: 3F.7 89.53,88.27 89.53,82.55 90.17,81.92 C12.2 90.81,81.28 90.81,105.41 90.17,106.05 C6.2 | 3B.7 37.47,90.81 37.47,106.68 C3.2 | v69.22,106.68 69.22,107.95 64.14,107.95 63.5,107.31 63.5,106.68 C4.2 | C10.2 59.69,81.92 59.05,82.55 59.05,88.27 3D.7 | C11.2 74.93,81.92 73.66,83.19 3E.7 75.56,90.81 75.56,105.41 74.93,106.05 C5.2 | C17.2 74.93,61.59 74.3,62.23 74.3,62.87 4E.7 | C18.2 90.17,56.52 89.53,57.15 89.53,62.87 4F.7 | C13.2 13.97,56.52 13.34,57.15 13.34,60.33 4A.8 | 4B.8 28.57,60.33 28.57,57.15 29.21,56.52 C14.2 29.21,55.24 29.84,54.61 29.84,30.48 | C15.2 44.45,60.96 4C.8 | C16.2 59.69,60.96 4D.8 | 6A.1 13.97,29.21 C19.2 13.97,34.29 5A.8 | 6B.1 29.21,29.21 C20.2 | 5B.8 29.21,34.29 C20.2 | 29.84,30.48 29.84,22.23 6B.4 | 6B.12 33.66,15.88 33.66,14.61 6B.10 | C24.2 90.17,31.11 89.53,31.75 89.53,37.47 5F.7 | 5D.13 65.41,46.35 65.41,47.62 5D.14 | v69.85,45.72 71.75,43.81 71.75,40.01 5E.7 74.93,36.83 C23.2 71.75,30.48 71.75,23.5 | 6C.1 44.45,29.21 C21.2 44.45,34.29 5C.8 | 5D.8 59.69,34.29 C22.2 59.69,29.21 6D.1 60.33,26.04 60.33,22.23 6D.4 | 6E.12 79.38,15.88 79.38,14.61 6E.10 | 69.22,14.61 71.12,12.7 | 71.12,12.7 6E.8 | 69.22,14.61 6D.12 | 71.12,12.7 71.75,13.34 | 71.75,13.34 6E.6 | 71.75,13.34 71.75,23.5 | 71.75,23.5 6E.2 | 69.22,14.61 67.31,12.7 6D.10 | 29.84,30.48 C20.2 | v6.35,64.77 6.35,76.83 5.71,77.47 C2.-
  Bottom 0.254: PL1.2 106.05,81.28 104.78,80.01 92.08,80.01 90.81,81.28 C12.2 | C2.- 5.71,80.01 12.06,80.01 13.34,81.28 C7.2 14.61,81.28 15.88,80.01 21.59,80.01 22.23,80.64 29.21,80.64 C8.2 29.84,81.28 31.11,80.01 42.55,80.01 43.81,81.28 C9.2 45.09,81.28 46.35,80.01 52.07,80.01 53.34,81.28 C10.2 60.33,81.28 61.59,80.01 68.58,80.01 69.85,81.28 C11.2 | C5.2 v69.22,106.68 | 3B.7 36.83,88.9 38.1,90.17 44.45,90.17 45.09,90.81 54.61,90.81 56.52,88.9 3D.7 | 3F.7 87.63,88.9 86.36,87.63 76.83,87.63 75.56,88.9 3E.7 | C18.2 83.82,55.88 82.55,54.61 76.83,54.61 75.56,55.88 C17.2 74.3,55.88 73.66,55.24 66.04,55.24 65.41,54.61 61.59,54.61 60.33,55.88 C16.2 57.15,55.88 55.88,54.61 46.35,54.61 45.09,55.88 C15.2 38.1,55.88 36.83,54.61 31.11,54.61 29.84,55.88 C14.2 | C13.2 14.61,55.88 17.78,59.05 24.77,59.05 26.67,60.96 4B.8 | 6B.12 34.29,17.78 32.38,19.68 28.57,19.68 6B.4 | C19.2 14.61,30.48 15.88,29.21 21.59,29.21 22.86,30.48 C20.2 | C1.- 6.35,12.06 9.53,12.06 11.43,10.16 6A.8 13.97,10.16 15.24,11.43 30.48,11.43 | 30.48,11.43 31.75,12.7 6B.10 39.37,12.7 41.91,10.16 6C.8 44.45,10.16 45.72,11.43 60.96,11.43 | 30.48,11.43 29.21,10.16 6B.8 | 76.83,31.75 85.72,31.75 86.36,32.38 102.87,32.38 103.5,33.02 PL1.39 | 76.83,31.75 75.56,30.48 C23.2 | v69.85,45.72 5D.13 | 76.83,31.75 79.38,29.21 88.27,29.21 89.53,30.48 C24.2 | C21.2 45.09,30.48 46.35,29.21 55.88,29.21 57.15,27.94 6D.1 | 6E.10 82.55,12.7 85.09,10.16 6F.8 | 60.96,11.43 62.23,12.7 6D.10 | 60.96,11.43 59.69,10.16 6D.8 | 6E.2 6E.15 | 6D.4 62.23,20.32 64.77,17.78 6D.12 69.85,17.78 72.39,20.32 6E.4 74.93,20.32 76.83,18.41 79.38,18.41 80.01,17.78 6E.12
  Bottom 0.254: v6.35,64.77 10.16,60.96 4A.8
IFETCH  (via drill 0.61)
  Top 0.254: v70.48,86.36 70.48,108.58 59.05,108.58 52.07,101.6 3B.13 | v102.87,85.72 102.87,57.78 103.5,57.15 106.68,57.15 PL1.22
  Bottom 0.254: v70.48,86.36 71.75,85.09 102.23,85.09 v102.87,85.72
INHIBIT
  Top 0.254: 78.11,69.85 78.11,88.27 3E.9 | 78.11,69.85 78.11,47.62 5E.5 | 78.11,69.85 82.55,69.85 83.19,69.22 83.19,67.94 4E.9
  Bottom 0.254: 3E.9 3F.6
INHSET  (via drill 0.61)
  Top 0.254: 3E.10 80.64,94.61 80.64,95.89 3E.11 78.11,99.69 v78.11,111.76 | 31.75,110.49 21.59,110.49 18.41,107.31 18.41,100.97 3A2.4 | 31.75,110.49 31.75,84.45 31.11,83.82 31.11,69.22 v31.75,68.58 | 31.75,110.49 v33.02,111.76 | 4B.12 TP2.1
  Bottom 0.254: v31.75,68.58 4B.12 | v33.02,111.76 v78.11,111.76
INTDIS  (via drill 0.61)
  Top 0.254: v78.11,20.32 78.11,41.91 76.2,41.91 74.93,40.64 5E.6 | v111.12,19.05 112.39,20.32 112.39,55.24 v111.76,55.88
  Bottom 0.254: v78.11,20.32 79.38,19.05 v111.12,19.05 | v111.76,55.88 109.22,58.42 PL1.20
INTGNT  (via drill 0.61)
  Top 0.254: v40.01,101.6 41.27,100.33 41.27,88.27 43.81,85.72 43.81,83.82 48.9,78.74 48.9,67.94 46.99,66.04 v46.99,60.33 | v105.41,54.61 105.41,52.7 104.14,51.44 PL1.25
  Bottom 0.254: v40.01,101.6 39.37,101.6 36.83,104.14 3B.1 | v46.99,60.33 50.8,56.52 58.42,56.52 59.05,57.15 71.12,57.15 71.75,56.52 73.66,56.52 74.3,57.15 99.69,57.15 100.33,56.52 101.6,56.52 103.5,54.61 v105.41,54.61
IO6004  (via drill 0.61)
  Top 0.254: 5E.13 83.19,52.7 83.19,61.59 4E.8 | v9.53,88.27 v9.53,76.2 9.53,67.94 v10.16,67.31
  Bottom 0.254: v9.53,76.2 4A.2 | v9.53,88.27 3A1.7 | v10.16,67.31 36.83,67.31 37.47,66.67 38.1,66.67 40.01,64.77 74.93,64.77 76.2,63.5 4E.8
IR3  (via drill 0.61)
  Top 0.254: v102.23,45.72 102.23,38.1 101.6,37.47 101.6,34.92 100.33,33.66 100.33,24.77 101.6,23.5 101.6,11.43 95.25,11.43 94.61,12.06 94.61,15.88 6F.12
  Bottom 0.254: v102.23,45.72 99.69,48.26 5F.12
IR4  (via drill 0.61)
  Top 0.254: v79.38,4.45 87.63,12.7 6F.7 | v22.86,5.08 15.88,12.06 v15.88,61.59
  Bottom 0.254: 4B.6 4A.11 v15.88,61.59 | v79.38,4.45 78.74,5.08 v22.86,5.08
IR5
  Top 0.254: 6F.10 98.42,14.61 98.42,48.9 5F.13
IR6  (via drill 0.61)
  Top 0.254: v23.5,68.58 24.13,67.94 24.13,64.77 25.4,63.5 4B.7 | 6C.14 52.7,24.77 52.7,31.11 48.9,34.92 48.9,53.98 49.53,54.61 50.8,54.61 50.8,58.42 48.9,60.33 48.9,61.59 4C.10
  Bottom 0.254: 6C.4 44.45,20.32 46.99,22.86 6C.14 | 4B.7 29.21,63.5 30.48,62.23 48.26,62.23 49.53,63.5 4C.10 | v23.5,68.58 4A.12
IR7
  Top 0.254: 48.26,12.7 45.09,12.7 45.09,13.34 6C.6 | 48.26,12.7 6C.10 | 48.26,12.7 48.26,66.04 4C.12
  Bottom 0.254: 4C.12 49.53,68.58 48.26,69.85 39.37,69.85 38.73,70.48 37.47,70.48 36.83,69.85 30.48,69.85 29.21,71.12 4B.4 4A.13
IR8  (via drill 0.61)
  Top 0.254: v46.99,17.78 46.99,21.59 6C.2 | 4C.15 53.34,73.66 53.34,20.32 6C.12 | v45.72,72.39 47.62,74.3 v47.62,76.2
  Bottom 0.254: 4A.14 4B.3 29.21,73.66 30.48,72.39 36.83,72.39 37.47,71.75 41.27,71.75 41.91,72.39 v45.72,72.39 | v46.99,17.78 6C.12 | 4C.15 v47.62,76.2
IR9  (via drill 0.61)
  Top 0.254: v69.22,96.52 68.58,95.89 v68.58,86.36 | v41.27,87 41.27,78.11 4C.2
  Bottom 0.254: 4B.2 29.21,76.2 30.48,77.47 40.64,77.47 41.91,76.2 4C.2 | v68.58,86.36 67.31,85.09 46.99,85.09 45.72,86.36 41.91,86.36 v41.27,87 | v69.22,96.52 3E.4
IR10  (via drill 0.61)
  Top 0.254: v29.84,64.77 29.84,76.83 4B.1 27.94,83.19 v30.48,85.72 | v69.85,84.45 71.12,83.19 71.12,76.2 4E.3
  Bottom 0.254: v29.84,64.77 38.73,64.77 40.01,63.5 4C.7 | v69.85,84.45 46.35,84.45 45.09,85.72 v30.48,85.72
IR11
  Top 0.254: 4C.5 40.01,71.75 40.01,74.3 38.1,76.2 4B.15
  Bottom 0.254: 4E.2 72.39,76.2 71.12,74.93 39.37,74.93 38.1,76.2 4B.15
LOADIR  (via drill 0.61)
  Top 0.254: v57.15,59.05 56.52,59.69 v56.52,90.17 | 6F.9 95.25,10.16 93.34,12.06 93.34,93.34 3F.11
  Bottom 0.254: v57.15,59.05 53.98,59.05 52.07,60.96 4C.9 | v56.52,90.17 74.93,90.17 80.01,95.25 93.98,95.25 95.25,96.52 3F.11
MEMSEL
  Bottom 0.254: 4E.12 82.55,73.66 86.36,77.47 104.78,77.47 106.05,78.74 PL1.4
N$1
  Top 0.254: 3B.11 42.55,97.16 42.55,98.42 3B.12
N$2
  Bottom 0.254: 3B.6 3B.9
N$3  (via drill 0.61)
  Top 0.254: 3B.8 TP11.1 | 87,87 87,99.69 3F.2 | 87,87 87,75.56 4F.3 | v87.63,87 87,87
  Bottom 0.254: v87.63,87 76.2,87 75.56,87.63 46.99,87.63 TP11.1
N$4  (via drill 0.61)
  Top 0.254: 3B.10 TP8.1 57.15,105.41 60.33,105.41 60.33,100.97 59.69,100.33 57.15,100.33 53.98,97.16 53.98,73.03 v54.61,72.39
  Bottom 0.254: 4F.5 87.63,68.58 86.36,69.85 76.2,69.85 74.93,68.58 4E.5 71.75,68.58 70.48,69.85 57.15,69.85 v54.61,72.39
N$5  (via drill 0.61)
  Top 0.254: 5E.1 74.93,53.34 77.47,55.88 77.47,64.14 v76.83,64.77 v76.83,100.33
  Bottom 0.254: v76.83,64.77 85.72,64.77 87,66.04 4F.6 | v76.83,100.33 68.58,100.33 67.31,101.6 3D.13
N$6  (via drill 0.61)
  Top 0.254: TP9.1 3D.5 | v71.75,95.25 71.75,99.69 3E.2
  Bottom 0.254: v71.75,95.25 60.96,95.25 59.69,93.98 3D.5
N$7  (via drill 0.61)
  Top 0.254: v76.83,27.94 v76.83,40.64 | v102.23,26.67 105.41,29.84 v105.41,31.75 | v111.12,31.75 111.76,32.38 111.76,54.61 110.49,55.88 v110.49,58.42
  Bottom 0.254: v76.83,40.64 77.47,40.64 80.01,43.18 5E.10 | v76.83,27.94 78.11,26.67 92.71,26.67 95.25,24.13 99.69,24.13 v102.23,26.67 | v105.41,31.75 v111.12,31.75 | v110.49,58.42 111.12,59.05 111.12,93.34 109.86,93.34 97.79,105.41 91.44,105.41 | 91.44,105.41 90.17,104.14 3F.1 | 91.44,105.41 22.86,105.41 21.59,104.14 3A2.2
N$8  (via drill 0.61)
  Top 0.254: v91.44,46.99 92.71,48.26 92.71,61.59 v92.08,62.23 | 3F.12 98.42,97.16 98.42,65.41 4F.8
  Bottom 0.254: v91.44,46.99 87.63,46.99 86.36,45.72 5E.11 | v92.08,62.23 93.34,63.5 4F.8
N$9  (via drill 0.61)
  Top 0.254: v23.5,85.72 23.5,98.42 3A2.3 | v70.48,50.8 70.48,69.85 69.85,70.48 v69.85,83.19
  Bottom 0.254: v23.5,85.72 26.04,83.19 v69.85,83.19 73.66,83.19 74.93,84.45 105.41,84.45 107.95,81.92 107.95,69.85 101.6,69.85 97.79,66.04 4F.9 | v70.48,50.8 5E.2
N$10  (via drill 0.61)
  Top 0.254: 5F.1 90.17,53.34 91.44,54.61 91.44,61.59 90.81,62.23 90.81,69.22 4F.4 | v24.77,69.85 22.86,71.75 v22.86,81.92 | v74.93,83.19 76.2,81.92 76.2,72.39 | 76.2,72.39 76.2,68.58 4E.6 | 76.2,72.39 v75.56,72.39
  Bottom 0.254: v24.77,69.85 25.4,69.85 26.67,68.58 4B.5 | v22.86,81.92 23.5,82.55 69.22,82.55 69.85,81.92 73.66,81.92 v74.93,83.19 | v75.56,72.39 86.36,72.39 87.63,71.12 4F.4
N$11  (via drill 0.61)
  Top 0.254: v64.14,72.39 63.5,73.03 63.5,97.79 62.23,99.06 3D.3
  Bottom 0.254: v64.14,72.39 71.12,72.39 72.39,71.12 4E.4
N$12  (via drill 0.61)
  Top 0.254: TP6.1 3D.4 59.05,97.16 59.05,97.79 v62.23,97.79
  Bottom 0.254: v62.23,97.79 86.36,97.79 87.63,99.06 3F.3
N$13  (via drill 0.61)
  Top 0.254: v99.69,39.37 99.06,40.01 99.06,70.48 v99.69,71.12
  Bottom 0.254: v99.69,39.37 95.25,39.37 93.98,40.64 5F.6 | v99.69,71.12 4F.11
N$14  (via drill 0.61)
  Top 0.254: v83.19,92.71 83.19,78.11 4E.13
  Bottom 0.254: v83.19,92.71 93.98,92.71 95.25,93.98 3F.10
N$15
  Top 0.254: 6E.14 78.74,25.4 78.74,66.04 4E.10
N$16  (via drill 0.61)
  Top 0.254: v85.09,46.99 v85.09,43.18
  Bottom 0.254: v85.09,46.99 76.2,46.99 74.93,45.72 5E.4 | v85.09,43.18 5F.5
N$17  (via drill 0.61)
  Top 0.254: v70.48,49.53 69.22,50.8 69.22,59.69 67.94,60.96 67.94,76.83 67.31,77.47 v68.58,78.74 | v85.09,80.01 84.45,79.38 84.45,76.83 86.36,74.93 v86.36,71.12
  Bottom 0.254: v70.48,49.53 71.12,49.53 72.39,48.26 5E.3 | v68.58,78.74 69.85,80.01 v85.09,80.01 | v86.36,71.12 87.63,69.85 93.98,69.85 95.25,68.58 4F.10
N$18  (via drill 0.61)
  Top 0.254: v92.08,43.18 92.71,42.55 92.71,22.86 90.17,20.32 6F.4 | 3F.8 93.98,86.36 93.98,45.72 5F.10
  Bottom 0.254: v92.08,43.18 5F.10
N$19
  Top 0.254: 6F.14 94.61,24.77 94.61,28.57 95.25,29.21 96.52,29.21 5F.8
N$20  (via drill 0.61)
  Top 0.254: v38.1,108.58 38.1,88.27 32.38,82.55 32.38,74.3 4B.13 | v91.44,108.58 94.61,105.41 94.61,100.97 95.25,100.33 97.79,100.33 99.06,99.06 99.06,76.83 v99.69,76.2 | 5F.11 94.61,47.62 94.61,53.98 95.25,54.61 96.52,54.61 96.52,60.96 94.61,62.87 94.61,74.3 4F.13
  Bottom 0.254: v38.1,108.58 v91.44,108.58 | v99.69,76.2 4F.13
N$28
  Top 0.254: 4A.7 TP1.1 8.26,65.41 8.26,99.69 3A1.2
N$29
  Top 0.254: 4A.9 TP3.1 22.23,61.59 22.23,79.38 21.59,80.01 21.59,87.63 3A2.8
N$35  (via drill 0.61)
  Top 0.254: v85.09,74.93 83.82,76.2 83.82,92.08 84.45,92.71 84.45,93.34 83.82,93.98 v83.82,99.06
  Bottom 0.254: v85.09,74.93 93.98,74.93 95.25,73.66 4F.12 | v83.82,99.06 82.55,100.33 78.11,100.33 76.83,99.06 3E.3
N$36  (via drill 0.61)
  Top 0.254: v25.4,64.77 26.04,65.41 v26.04,88.27
  Bottom 0.254: v25.4,64.77 22.86,64.77 21.59,63.5 4A.10 | v26.04,88.27 30.48,92.71 44.45,92.71 45.09,92.08 56.52,92.08 57.15,92.71 71.12,92.71 72.39,91.44 3E.6
N$37  (via drill 0.61)
  Top 0.254: v24.13,78.74 24.77,79.38 v24.77,109.22 | v100.97,41.91 100.33,42.55 v100.33,45.72
  Bottom 0.254: v24.13,78.74 21.59,76.2 4A.15 | v24.77,109.22 26.04,110.49 42.55,110.49 43.18,111.12 74.3,111.12 74.93,110.49 93.98,110.49 94.61,111.12 113.03,92.71 113.03,44.45 106.05,44.45 105.41,43.81 105.41,41.91 v100.97,41.91 | v100.33,45.72 99.06,46.99 92.71,46.99 91.44,48.26 5F.3
N$38
  Top 0.254: 6A.6 10.79,17.14 10.79,48.9 5A.2
N$39
  Top 0.254: 4E.1 71.75,80.64 71.75,92.08 3E.5
N$40
  Top 0.254: 6A.14 18.41,24.77 18.41,28.57 19.05,29.21 20.32,29.21 20.32,33.02 18.41,34.92 18.41,36.2 5A.10
N$41
  Bottom 0.254: 6A.2 9.53,25.4 2.54,32.38 2.54,38.1 5A.7
N$42
  Top 0.254: 6A.4 15.24,22.86 15.24,40.64 5A.5
N$43
  Top 0.254: 6A.10 22.23,14.61 22.23,48.9 5A.15
N$44
  Top 0.254: 6A.12 17.78,20.32 17.78,40.64 5A.12
N$45  (via drill 0.61)
  Top 0.254: 6D.14 67.94,24.77 v67.94,49.53 68.58,50.16 68.58,59.05 v67.94,59.69 | v46.99,77.47 44.45,74.93 41.27,74.93 41.27,76.83 38.73,79.38 38.73,105.41 v43.18,109.86 | v94.61,109.86 109.22,95.25 v109.22,66.04
  Bottom 0.254: v67.94,49.53 60.96,49.53 59.69,50.8 5D.2 | v46.99,77.47 63.5,77.47 64.77,76.2 4D.15 | v94.61,109.86 v43.18,109.86 | v109.22,66.04 107.95,64.77 100.97,64.77 97.16,60.96 70.48,60.96 69.22,59.69 v67.94,59.69
N$46  (via drill 0.61)
  Top 0.254: v63.5,29.21 63.5,38.1 | 63.5,38.1 5D.11 | 63.5,38.1 63.5,60.96 4D.10
  Bottom 0.254: v63.5,29.21 59.69,25.4 6D.2
N$47
  Top 0.254: 60.96,40.64 60.96,17.78 6D.6 | 60.96,40.64 5D.5 | 60.96,40.64 60.96,60.96 4D.7
N$48  (via drill 0.61)
  Top 0.254: 4D.1 59.69,78.74 60.96,80.01 v60.96,88.9 60.33,89.53 60.33,92.08 59.69,92.71 57.15,92.71 55.24,90.81 55.24,73.03 55.88,72.39 v55.88,57.78 | TP5.1 5B.1 | 5C.1 v43.18,58.42
  Bottom 0.254: v60.96,88.9 3D.8 | 5C.1 41.91,53.34 40.64,52.07 30.48,52.07 29.21,53.34 5B.1 | v55.88,57.78 55.24,58.42 50.16,58.42 46.99,61.59 46.35,61.59 v43.18,58.42
N$50  (via drill 0.61)
  Top 0.254: v71.12,70.48 71.75,69.85 v71.75,57.78 | v57.15,57.78 55.88,56.52 55.88,38.73 v55.24,38.1
  Bottom 0.254: 5A.11 21.59,40.64 22.23,40.01 26.04,40.01 26.67,39.37 31.75,39.37 34.29,36.83 48.26,36.83 49.53,38.1 5C.10 v55.24,38.1 | v71.12,70.48 67.94,70.48 67.31,71.12 4D.13 | v57.15,57.78 v71.75,57.78
N$51  (via drill 0.61)
  Top 0.254: v54.61,52.07 v54.61,68.58
  Bottom 0.254: 40.64,49.53 41.91,50.8 5C.2 | 40.64,49.53 38.1,46.99 15.24,46.99 13.97,48.26 5A.3 | v54.61,52.07 52.07,49.53 40.64,49.53 | v54.61,68.58 4D.5
N$52  (via drill 0.61)
  Top 0.254: v45.72,33.02 45.09,33.66 45.09,36.2 5C.7 | v62.23,86.36 62.23,72.39 4D.12
  Bottom 0.254: v45.72,33.02 20.32,33.02 5A.6 1.91,40.64 1.91,78.74 10.16,87 36.2,87 37.47,88.27 41.27,88.27 42.55,87 61.59,87 v62.23,86.36
N$53  (via drill 0.61)
  Top 0.254: 34.29,36.83 33.66,36.2 33.66,34.29 33.02,33.66 33.02,25.4 6B.14 | 34.29,36.83 5B.10 | v31.75,49.53 32.38,48.9 32.38,38.73 34.29,36.83 | v56.52,26.67 56.52,46.35 5D.3
  Bottom 0.254: v31.75,49.53 29.21,52.07 26.67,52.07 26.04,51.44 23.5,51.44 21.59,49.53 10.79,49.53 10.79,47.62 5A.4 | v56.52,26.67 40.64,26.67 36.83,22.86 6B.14
N$54  (via drill 0.61)
  Top 0.254: 26.04,17.14 25.4,17.78 25.4,48.26 5B.2 | 26.04,17.14 6B.6 | v54.61,40.64 53.98,40.01 53.98,13.34 52.07,11.43 26.04,11.43 26.04,17.14
  Bottom 0.254: 5A.14 21.59,48.26 24.13,50.8 5B.2 | v54.61,40.64 5D.6
N$55  (via drill 0.61)
  Top 0.254: 6B.2 26.04,27.3 26.04,36.2 5B.7 | v17.78,41.91 17.78,43.18 5A.13
  Bottom 0.254: v17.78,41.91 17.78,39.37 22.23,39.37 | 22.23,39.37 25.4,39.37 26.67,38.1 5B.7 | 22.23,39.37 22.23,37.47 26.04,33.66 31.75,33.66 32.38,34.29 60.96,34.29 64.77,38.1 5D.10
N$59  (via drill 0.61)
  Top 0.254: v6.35,41.91 4.45,43.81 4.45,76.2 2.54,78.11 v2.54,91.44 | v68.58,99.06 67.94,98.42 67.94,93.34 3D.9
  Bottom 0.254: v6.35,41.91 13.97,41.91 5A.9 | v2.54,91.44 11.43,100.33 54.61,100.33 55.24,99.69 56.52,99.69 57.15,100.33 67.31,100.33 v68.58,99.06
N$61  (via drill 0.61)
  Top 0.254: v69.22,60.96 68.58,61.59 v68.58,77.47 | v85.72,78.11 86.36,78.74 86.36,100.33 83.82,100.33 82.55,99.06 3E.12
  Bottom 0.254: v68.58,77.47 85.09,77.47 v85.72,78.11 86.36,78.74 4F.1 | 4D.9 v69.22,60.96
N$70  (via drill 0.61)
  Top 0.254: v85.09,90.17 v85.09,93.98
  Bottom 0.254: v85.09,90.17 83.82,90.17 82.55,88.9 3E.8 | v85.09,93.98 3F.5
N$71  (via drill 0.61)
  Top 0.254: v92.08,76.2 92.71,76.83 v92.71,96.52
  Bottom 0.254: 4F.2 v92.08,76.2 | v92.71,96.52 3F.4
N$72
  Top 0.254: 3B.3 34.92,99.69 34.92,100.97 3B.2
N$74
  Bottom 0.254: 3B.4 36.83,96.52 38.1,97.79 54.61,97.79 55.24,98.42 56.52,98.42 57.15,97.79 60.96,97.79 62.23,96.52 3D.11
RDF
  Top 0.254: 4A.6 10.79,67.94 10.79,99.69 3A1.3
  Bottom 0.254: 6B.15 34.29,25.4 33.02,24.13 9.53,24.13 1.27,32.38 1.27,99.06 8.89,99.06 11.43,101.6 3A1.3
RIF  (via drill 0.61)
  Top 0.254: 4A.4 14.61,73.03 14.61,79.38 13.97,80.01 12.7,80.01 12.7,86.36 14.61,88.27 14.61,94.61 3A1.5 | v57.78,6.35 61.59,10.16 61.59,20.95 6D.15 | v13.34,6.99 7.62,12.7 7.62,24.77 2.54,29.84 2.54,64.77 v3.17,65.41
  Bottom 0.254: v57.78,6.35 57.15,6.99 v13.34,6.99 | v3.17,65.41 8.89,71.12 4A.4
RMEN  (via drill 0.61)
  Top 0.254: 4A.1 12.06,79.38 12.06,88.27 3A1.8 | 76.83,20.32 76.83,24.77 6E.1 | 76.83,20.32 78.11,19.05 83.19,19.05 83.19,36.2 82.55,36.83 83.19,37.47 83.19,38.73 5E.9 | v3.17,71.12 1.91,69.85 v1.91,12.7 | v52.7,8.26 55.88,5.08 76.83,5.08 76.83,20.32
  Bottom 0.254: v3.17,71.12 9.53,77.47 10.16,77.47 11.43,78.74 4A.1 | v1.91,12.7 4.45,10.16 10.16,10.16 12.06,8.26 v52.7,8.26
SELIR  (via drill 0.61)
  Top 0.254: v46.99,25.4 45.72,26.67 v45.72,27.94 | v31.75,26.67 30.48,27.94 v30.48,58.42 | v17.78,57.78 17.78,73.66 17.14,74.3 17.14,82.55 17.78,83.19 17.78,95.25 21.59,95.25 22.23,94.61 22.23,93.34 3A2.7
  Bottom 0.254: v45.72,27.94 44.45,29.21 39.37,29.21 36.83,26.67 v31.75,26.67 | v46.99,25.4 6C.15 | 4B.9 33.02,60.96 v30.48,58.42 18.41,58.42 v17.78,57.78
VCC  (via drill 0.61)
  Top 0.254: C22.1 64.77,29.84 65.41,29.21 65.41,28.57 6D.16 | C21.1 49.53,29.84 50.16,29.21 50.16,28.57 6C.16 | 6B.16 34.29,29.21 C20.1 | C13.1 19.05,55.24 19.68,54.61 19.68,53.98 5A.16 | v46.99,50.8 v46.99,45.72 | 5B.16 34.92,53.98 34.92,54.61 34.29,55.24 C14.1 33.66,55.88 33.66,47.62 5B.13 | 6F.3 87,24.77 87,26.04 6F.1 | 6E.16 80.64,28.57 80.64,29.21 80.01,29.84 C23.1 80.01,31.11 79.38,31.75 79.38,55.88 C17.1 80.01,55.24 80.64,54.61 80.64,53.98 5E.14 | v106.68,30.48 PL1.40 | v91.44,53.34 91.44,48.26 5F.4 | C16.1 64.77,55.24 65.41,54.61 65.41,53.98 5D.16 | C9.1 49.53,80.64 50.16,80.01 50.16,79.38 4C.16 | C7.1 19.05,80.64 19.68,80.01 19.68,79.38 4A.16 | C8.1 34.29,80.64 34.92,80.01 34.92,79.38 4B.16 | v60.96,78.74 60.96,73.66 4D.4 | 4D.16 65.41,79.38 65.41,80.01 64.77,80.64 C10.1 64.14,81.28 64.14,92.08 | 64.14,92.08 3D.10 | 64.14,92.08 64.14,97.16 3D.12 64.14,100.97 64.14,106.68 C4.1 64.77,106.05 65.41,105.41 65.41,104.78 3D.14 | C11.1 80.01,80.64 80.64,80.01 80.64,79.38 4E.14 | C12.1 95.25,80.64 95.89,80.01 95.89,79.38 4F.14 | C6.1 95.25,106.05 95.89,105.41 95.89,104.78 3F.14 99.06,104.14 100.97,102.23 100.97,100.97 100.33,100.33 v100.33,83.19 | C5.1 80.01,106.05 80.64,105.41 80.64,104.78 3E.14 | 3B.14 41.91,105.41 C3.1 | C1.+ 5.71,36.83 7.62,38.73 7.62,98.42 5.71,100.33 C2.+
  Bottom 0.254: C1.+ 5.71,34.29 14.61,34.29 18.41,30.48 C19.1 19.68,30.48 20.95,31.75 40.64,31.75 | 6A.16 21.59,27.94 22.86,29.21 32.38,29.21 33.66,30.48 C20.1 | 47.62,31.75 48.9,30.48 C21.1 | 40.64,31.75 47.62,31.75 | 40.64,31.75 36.83,27.94 6B.16 | 47.62,31.75 62.87,31.75 64.14,30.48 C22.1 | 5A.1 5A.16 21.59,53.34 25.4,57.15 36.2,57.15 | 47.62,51.44 49.53,53.34 5C.16 52.07,53.34 52.7,53.98 56.52,53.98 57.15,54.61 60.33,54.61 61.59,53.34 5D.16 67.31,53.34 68.58,54.61 75.56,54.61 76.83,53.34 5E.14 82.55,53.34 83.82,54.61 90.17,54.61 v91.44,53.34 5F.14 96.52,53.98 95.25,55.24 C18.1 | 47.62,51.44 v46.99,50.8 | v46.99,45.72 5C.13 | 36.2,57.15 47.62,57.15 48.9,55.88 C15.1 | 36.2,57.15 34.92,55.88 C14.1 | 47.62,51.44 44.45,54.61 38.1,54.61 36.83,53.34 5B.16 | 6F.16 6F.1 6E.16 79.38,27.94 78.11,29.21 68.58,29.21 67.31,27.94 6D.16 | C23.1 85.72,30.48 87,31.75 93.34,31.75 94.61,30.48 C24.1 v106.68,30.48 | 4A.16 21.59,78.74 22.86,80.01 29.84,80.01 31.11,78.74 4B.16 4C.1 4C.16 52.07,78.74 53.34,80.01 59.69,80.01 v60.96,78.74 4D.16 | 100.33,81.28 PL1.1 | 100.33,81.28 C12.1 94.61,81.28 93.34,82.55 81.92,82.55 80.64,81.28 C11.1 | C2.+ 6.35,102.23 6.99,102.23 11.43,106.68 3A1.1 3A2.1 21.59,106.68 22.86,107.95 37.47,107.95 38.73,106.68 C3.1 | 3D.14 3D.1 3B.14 | 78.11,107.95 79.38,106.68 C5.1 | 78.11,107.95 66.67,107.95 65.41,106.68 C4.1 | 78.11,107.95 90.81,107.95 91.44,107.31 93.98,107.31 94.61,106.68 C6.1 | v100.33,83.19 100.33,81.28
XTA  (via drill 0.61)
  Top 0.254: TP12.1 3F.13 | v101.6,99.06 108.58,92.08 108.58,78.74 106.68,76.83 PL1.6
  Bottom 0.254: v101.6,99.06 TP12.1
XTC  (via drill 0.61)
  Top 0.254: v52.07,102.87 52.07,111.12 39.37,111.12 33.66,105.41 33.66,95.89 3B.5 | v101.6,97.79 101.6,88.27 105.41,84.45 105.41,78.11 104.14,76.83 PL1.5
  Bottom 0.254: v52.07,102.87 52.7,103.5 56.52,103.5 57.15,102.87 90.17,102.87 95.25,97.79 v101.6,97.79

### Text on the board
Bottom: EMC6907 MMU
